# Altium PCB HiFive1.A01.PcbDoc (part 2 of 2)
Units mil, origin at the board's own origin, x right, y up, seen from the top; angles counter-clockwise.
Board outline 2700 x 2100 mil, 4 copper layers (Top Layer, GND, Power, Bottom Layer), stack 60.6 mil thick; 123 components, 93 nets, 495 pads, 264 vias.
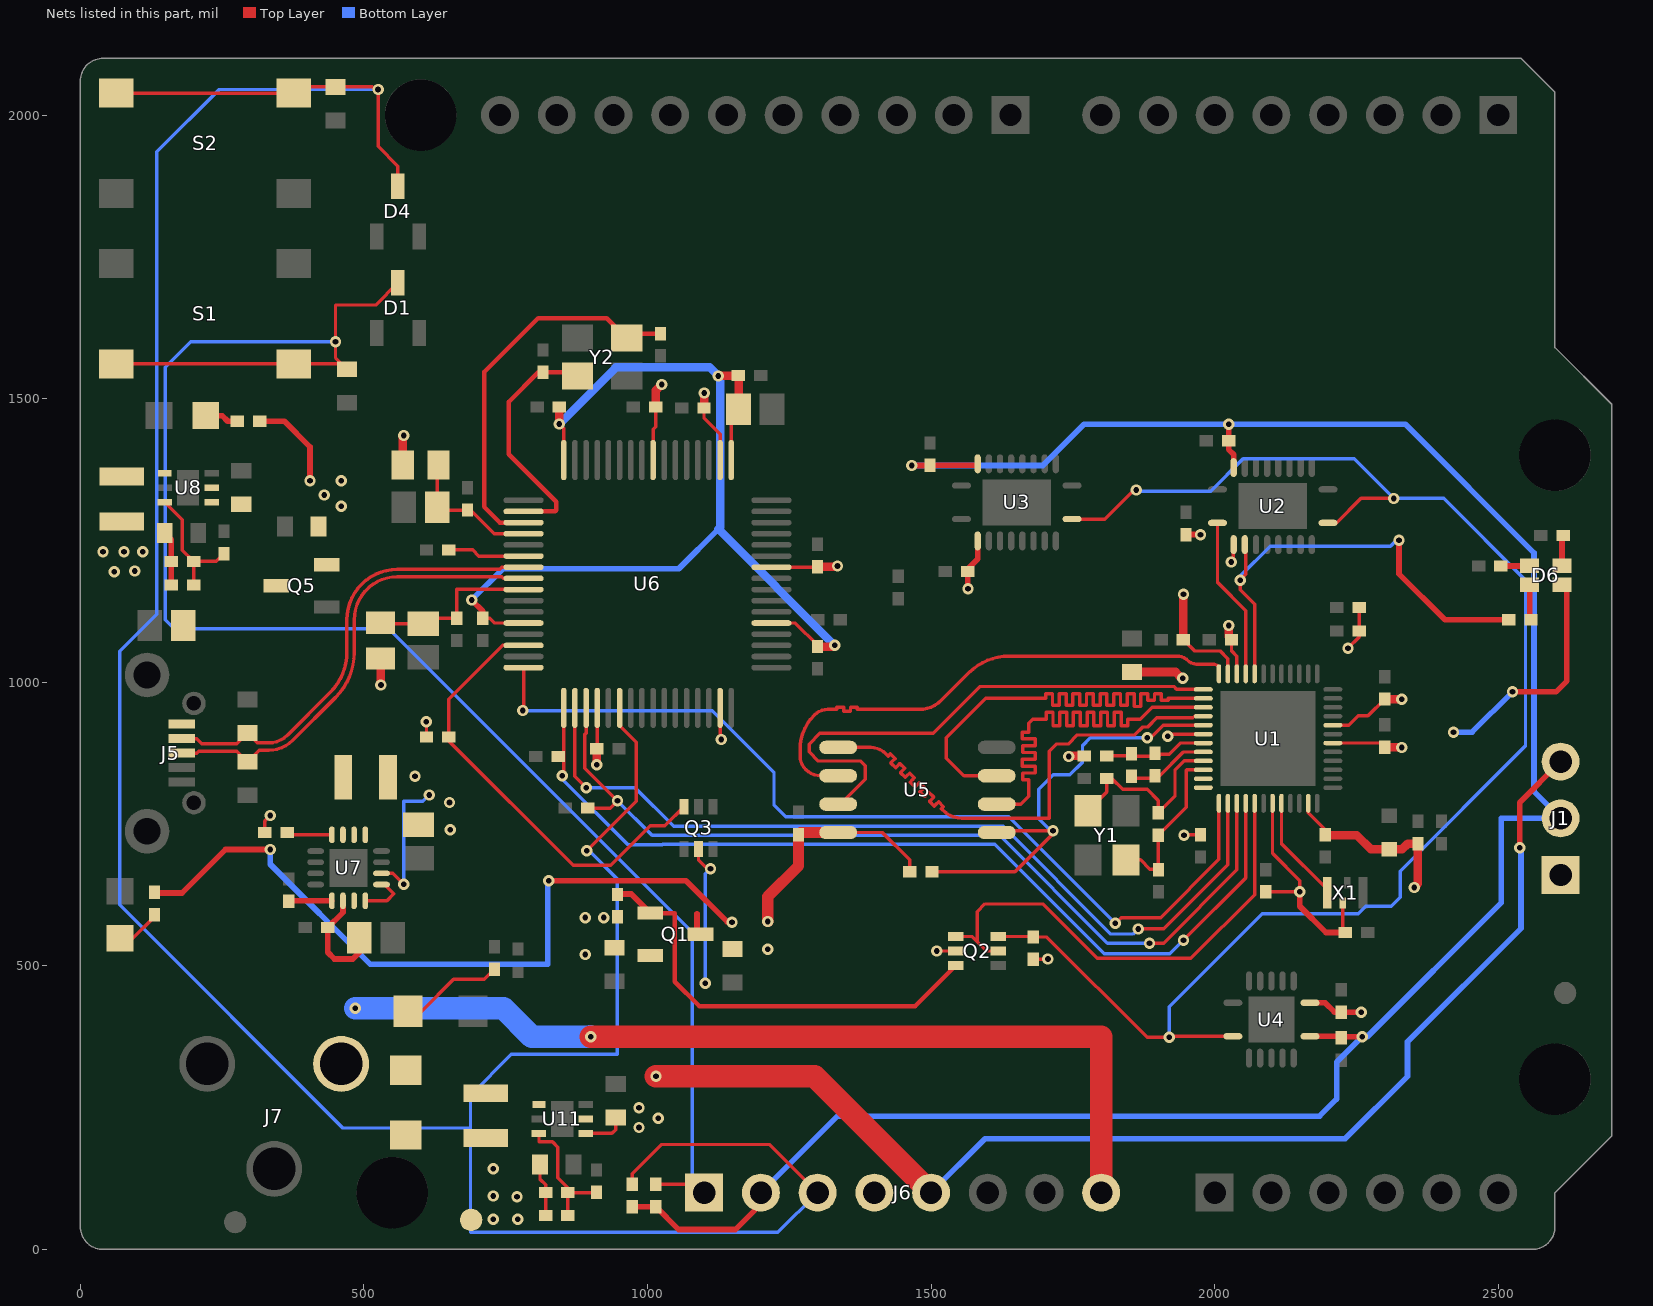
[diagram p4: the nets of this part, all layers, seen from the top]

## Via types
v1: diameter 20, hole 10, Top Layer to Bottom Layer, tented both sides, 264 vias

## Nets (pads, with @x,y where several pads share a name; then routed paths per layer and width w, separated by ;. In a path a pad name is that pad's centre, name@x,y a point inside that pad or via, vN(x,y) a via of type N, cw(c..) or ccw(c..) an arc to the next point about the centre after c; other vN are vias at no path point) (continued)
GPIO_22: R19.2 U1.44 U2.3 | length 842.3
  Top Layer w6: U2.3@2053.2,1242.56 2055,1240.76 2055,1190 v1(2045,1180) 2045,1163 2070.55,1137.45 U1.44@2070.55,1014.8
  Top Layer w10: v1(2325,1250) 2325,1191 2406,1110 R19.2@2518.31,1110
  Bottom Layer w6: v1(2045,1180) 2045,1187.23 2097.77,1240 2310,1240 2320,1250 v1(2325,1250)
GPIO_23: U1.45 U2.1 | length 286.8
  Top Layer w6: U2.1@2004.97,1280.94 2004.97,1176.03 2054.8,1126.2 U1.45@2054.8,1014.8
JTAG_TCK: U1.13 U6.16 | length 1638
  Top Layer w6: v1(780,950) 781.5,951.5 U6.16@781.5,1025.58 ; v1(1825,575) 1835,585 1905,585 2007.56,687.56 U1.13@2007.56,786.46
  Bottom Layer w6: v1(780,950) 1114,950 1223,841 1223,784 1244,763 1637,763 v1(1825,575)
JTAG_TDI: R12.1 U1.16 U6.17 | length 1656.2
  Top Layer w6: R12.1@842.68,869 R12.1@852.36,869 ; v1(850,835) 852.36,837.36 R12.1@852.36,869 ; U6.17@852.36,954.71 R12.1@852.36,869 ; v1(1945,545) 2054.8,654.8 U1.16@2054.8,786.46
  Bottom Layer w6: v1(850,835) 850,829.13 965.62,713.51 1026.51,713.51 1027,714 1612,714 1805,521 1921,521 v1(1945,545)
JTAG_TDO: U1.14 U6.18 | length 1546.9
  Top Layer w6: U6.18@872.05,954.71 872.05,833.95 v1(892,814) ; v1(1865,565) 1910,565 2023.31,678.31 U1.14@2023.31,786.46
  Bottom Layer w6: v1@891.32,814.68 v1(892,814) 978,814 1046,746 1627.13,746 1817.13,556 1856,556 v1(1865,565)
JTAG_TMS: R10.1 U1.15 U6.19 | length 1613
  Top Layer w6: U6.19@891.73,954.71 891.73,910.35 889.5,908.12 889.5,848.63 894.09,844.04 894.09,843.91 v1(947,791) 934,778 R10.1@894.68,778 ; v1(1885,540) 1910,540 2039.06,669.06 U1.15@2039.06,786.46
  Bottom Layer w6: v1(947,791) 1008,730 1621,730 1811,540 v1(1885,540)
LFCLK: U1.20 X1.3 | length 191.2
  Top Layer w6: U1.20@2117.8,786.46 2117.8,715.33 2198.5,634.63 X1.3@2198.5,628.64
NetC8_2: C8.2 C9.2 U1.8 | length 149.3
  Top Layer w6: C8.2@1850,830.31 1891.8,830.31 1895,833.51 1901.54,833.51 1945.04,877.01 U1.8@1980,877.01
NetC12_1: C12.1 R4.1 U1.9 Y1.1 | length 360.1
  Top Layer w6: Y1.1@1776.54,756.46 Y1.1@1776.54,773.31 1809.68,806.46 C12.1@1809.68,830 1819,830 1838,811 1881,811 1900.56,791.44 R4.1@1900.56,769.68 1930,799.12 1930,845 1946.26,861.26 U1.9@1980,861.26
NetC13_1: C13.1 R4.2 U1.10 Y1.3 | length 308.1
  Top Layer w6: Y1.3@1856.6,673.56 Y1.3@1843.46,686.69 1869.31,686.69 1885.88,670.12 1900.56,670.12 R4.2@1900.56,730.31 1950,779.75 1950,845 1950.51,845.51 U1.10@1980,845.51
NetC39_1: C39.1 U6.2 Y2.1 | length 430.1
  Top Layer w8: U6.2@781.5,1301.17 837.17,1301.17 839,1303 839,1318 755.08,1401.92 755.08,1494.08 807.32,1546.32 C39.1@816,1546.32 870.13,1546.32 Y2.1@876.69,1539.75
NetC40_1: C40.1 U6.3 Y2.3 | length 687.2
  Top Layer w8: U6.3@781.5,1281.49 739.51,1281.49 712,1309 712,1547 807,1642 927.99,1642 Y2.3@963.31,1606.68 972.68,1606.68 980.68,1614.68 C40.1@1023,1614.68
NetC45_1: C45.1 U7.9 | length 76.4
  Top Layer w10: C45.1@367.45,613.59 368.59,614.74 U7.9@443.4,614.74
NetC48_2: C48.2 R35.2 R36.1 U8.3 | length 226.2
  Top Layer w6: U8.3@148.66,1317.42 180,1286.08 180,1232.7 R35.2@199.69,1213.01 ; C48.2@199.69,1171.51 R35.2@199.69,1213.01 ; R36.1@253.16,1226.7 239.47,1213.01 R35.2@199.69,1213.01
NetC54_2: C54.2 R37.2 R39.1 U11.3 | length 236.8
  Top Layer w6: U11.3@808.66,204.41 808.66,189.5 832.5,189.5 842,180 842,126 859.69,108.31 R37.2@859.69,100 ; C54.2@859.69,60 R37.2@859.69,100 ; R39.1@909.37,92.37 909.37,100 R37.2@859.69,100
NetD6_1: D6.1 R19.1 | length 68.5
  Top Layer w10: R19.1@2557.68,1110 2555.46,1112.23 D6.1@2555.46,1172.13 D6.1@2560.87,1172.13
NetD6_2: D6.2 R18.1 | length 51
  Top Layer w10: R18.1@2504.68,1205 2554.87,1205 D6.2@2555.46,1205.59
NetD6_3: D6.3 R17.1 | length 54.1
  Top Layer w8: R17.1@2612.54,1257.08 R17.1@2614.37,1258.91
  Top Layer w10: D6.3@2612.54,1205.59 R17.1@2612.54,1257.08
NetD9_2: D9.2 R27.2 | length 59.5
  Top Layer w10: D9.2@221.34,1470 250,1470 260,1460 R27.2@276.69,1460
NetD10_2: D10.2 R28.2 | length 80.1
  Top Layer w6: D10.2@70,548.66 92.66,548.66 130.76,586.76 R28.2@130.76,590.31
NetD13_2: D13.2 J7.1
NetL1_1: L1.1 U7.1 U7.2 U7.3
NetL2_1: L2.1 U8.1
NetL3_1: L3.1 U11.1
NetQ1_1: Q1.1 Q2.3 R9.1 | length 769.9
  Top Layer w8: Q1.1@1005,593 1048,593 1048,472 1091,429 1472.19,429 Q2.3@1543.6,500.41
  Top Layer w10: R9.1@956,626.68 971.32,626.68 Q1.1@1005,593
NetQ3_6: Q3.6 R23.2 U6.14 | length 793.1
  Top Layer w6: U6.14@781.5,1064.95 744.95,1064.95 649.69,969.69 R23.2@649.69,903.22 649.69,896.31 869,677 935,677 1005,747 1030.79,747 Q3.6@1064.41,780.62
NetR24_1: R24.1 U6.6 | length 136.3
  Top Layer w6: R24.1@649.68,1233.22 691.78,1233.22 702.57,1222.43 U6.6@781.5,1222.43
NetR31_2: R31.2 U7.4 | length 80.4
  Top Layer w6: R31.2@364.69,735 368.81,730.88 U7.4@443.4,730.88
PLL_AVDD: C8.1 C9.1 R1.2 U1.7 | length 180
  Top Layer w6: R1.2@1809.69,870 1849.68,870 1850,869.68 1901.8,869.68 1905,872.88 1919.75,872.88 1939.63,892.76 U1.7@1980,892.76
QSPI_CS0: R13.1 U1.5 U5.1 | length 793.5
  Top Layer w6: R13.1@1501.68,665.93 1647.93,665.93 1715,733 v1(1715,738) 1639,738 1634,733 1617.76,733 U5.1@1615.76,735 ; v1(1881,902) 1887.13,902 1909.38,924.25 U1.5@1980,924.25
  Bottom Layer w6: v1(1715,738) 1715,734 1713,736 1690,759 1690,811 1715.75,836.75 1744.75,836.75 1767,859 1767,888 1781,902 v1(1881,902)
QSPI_DQ0: U1.4 U5.5 | length 952.3
  Top Layer w6: U5.5@1336.24,885 1393.44,885 cw(c1393.44,847.44) 1420,874 1424.26,869.78 1428.02,873.57 1436.55,865.13 1432.79,861.34 1429.04,857.54 1437.56,849.1 1441.32,852.89 1445.07,856.69 1453.6,848.24 1449.85,844.45 1446.09,840.66 1454.62,832.21 1458.37,836.01 1462.13,839.8 1470.66,831.36 1466.9,827.56 1463.15,823.77 1471.67,815.33 1475.43,819.12 1479.18,822.91 1487.71,814.47 1483.96,810.68 1480.2,806.88 1488.73,798.44 1492.48,802.23 1496.24,806.03 1504.77,797.58 1501.01,793.79 1497.25,790 1505.78,781.56 1509.54,785.35 1513.29,789.14 1521.82,780.7 1518.07,776.91 1521,774 ccw(c1554.02,807.02) 1554.02,760.32 1708,760.32 1708,878 1721,891 1742,891 1758,907 1859.13,907 1873.13,921 1881.96,921 1898,937.04 1961.7,937.04 1964.66,940 U1.4@1980,940
QSPI_DQ1: U1.3 U5.2 | length 951.4
  Top Layer w6: U5.2@1615.76,785 1658,785 1672,799 1672,822 1672,828 1661.79,828 1661.79,840 1672,840 1683.43,840 1683.43,852 1672,852 1660.57,852 1660.57,864 1672,864 1683.43,864 1683.43,876 1672,876 1661.79,876 1661.79,888 1672,888 1683.43,888 1683.43,900 1672,900 1660.57,900 1660.57,912 1672,912 1672,917 1672,927.93 1679.07,935 1703,935 1703,946.9 1715,946.9 1715,935 1715,923.1 1727,923.1 1727,935 1727,946.9 1739,946.9 1739,935 1739,923.1 1751,923.1 1751,935 1751,946.9 1763,946.9 1763,935 1763,923.1 1775,923.1 1775,935 1775,946.9 1787,946.9 1787,935 1787,923.1 1799,923.1 1799,935 1799,946.9 1811,946.9 1811,935 1811,923.1 1823,923.1 1823,935 1823,946.9 1835,946.9 1835,935 1835,923.1 1847,923.1 1847,935 1853,935 1868.92,935 1889.67,955.75 U1.3@1980,955.75
QSPI_DQ2: U1.2 U5.3 | length 951.4
  Top Layer w6: U5.3@1615.76,835 1558,835 1527,866 1527,902 1596.5,971.5 1651,971.5 1702,971.5 1702,979.74 1714,979.74 1714,971.5 1714,959.61 1726,959.61 1726,971.5 1726,979.74 1738,979.74 1738,971.5 1738,959.61 1750,959.61 1750,971.5 1750,979.76 1762,979.76 1762,971.5 1762,959.61 1774,959.61 1774,971.5 1774,979.75 1786,979.75 1786,971.5 1786,959.61 1798,959.61 1798,971.5 1798,979.74 1810,979.74 1810,971.5 1810,959.61 1822,959.61 1822,971.5 1822,979.74 1834,979.74 1834,971.5 1834,959.61 1846,959.61 1846,971.5 1846,979.76 1858,979.76 1858,971.5 1858,957.2 1870,957.2 1870,971.5 1870,979.75 1882,979.75 1882,971.5 1882,968.45 1894,968.45 1894,971.5 1894,979.78 1906,979.78 1906,971.5 1906,968.45 1918,968.45 1918,971.5 1924,971.5 U1.2@1980,971.5
QSPI_DQ3: U1.1 U5.7 | length 952.1
  Top Layer w6: U5.7@1336.24,785 1340,785 1384,829 1384,853 1376,861 1301,861 1285,877 1285,891 1304,910 1504,910 1586.48,992.48 1927.52,992.48 1932.76,987.24 U1.1@1980,987.24
QSPI_SCK: U1.48 U5.6 | length 952.6
  Top Layer w6: U5.6@1336.24,835 1305.56,835 cw(c1305.56,872.56) 1279,846 cw(c1303.14,870.14) 1269,870.14 1269,881.64 cw(c1354.36,881.64) 1294,942 cw(c1318.14,917.86) 1318.14,952 1328,952 1334,952 1334,955.5 1346,955.5 1346,952 1346,948.5 1358,948.5 1358,952 1358,955.5 1370,955.5 1370,952 1382,952 1479.37,952 ccw(c1479.37,1006.63) 1518,968 1566.71,1016.71 cw(c1637.42,946) 1637.42,1046 1933.69,1046 cw(c1933.69,1018.69) 1953,1038 ccw(c1967.49,1052.49) 1967.49,1032 1996.55,1032 cw(c1996.55,1016.43) 2007.56,1027.44 U1.48@2007.56,1014.8
RESET: D4.3 D5.1 J6.3 R6.2 S2.3 S2.4 U6.22 | length 5482.3
  Top Layer w6: S2.4@63.5,2038.58 S2.3@376.5,2038.58 387.44,2049.53 D5.1@450,2049.53 514.53,2049.53 519.06,2045 v1(525,2045) 525,1945 560,1910 D4.3@560,1874.29 ; v1(893,703) 980,790 980,894 950.79,923.21 U6.22@950.79,954.71 ; R6.2@973.1,114.69 973.1,133.1 1025,185 1215,185 J6.3@1300,100
  Bottom Layer w6: v1(525,2045) 245,2045 135,1935 135,1120 69.35,1054.35 69.35,607.65 463,214 688,214 ; v1(893,703) 897,703 947,653 947,344 760,344 688,272 688,214 ; J6.3@1300,100 1230,30 688,30 688,214
TSLR_OE: Q2.6 R11.2 U2.10 U3.10 U4.8 | length 2747.3
  Top Layer w6: Q2.6@1618.4,551.59 1679.09,551.59 R11.2@1680,550.69 1704.31,550.69 1881,374 v1(1920,374) 1921.76,375.76 U4.8@2032.08,375.76 ; U3.10@1748.54,1287.56 1806.56,1287.56 1858,1339 v1(1862,1339) ; U2.10@2199.85,1280.94 2214.94,1280.94 2258,1324 v1(2316,1324)
  Bottom Layer w6: v1(1862,1339) 1864,1337 1993,1337 2050,1394 2246,1394 v1(2316,1324) 2404,1324 2548,1180 2548,888 2327,667 2327,621 2311,605 2266,605 2253,592 2084,592 1920,428 v1(1920,374)
USB_D_N: D8.1 J5.2 U6.7 | length 815.2
  Top Layer w6: J5.2@178.74,900.59 205.36,900.59 214.45,891.5 275.85,891.5 D8.1@294.82,910.47 312.29,893 332.05,893 ccw(c332.05,939.95) 365.25,906.75 440.71,982.21 ccw(c370,1052.92) 470,1052.92 470,1110 cw(c559,1110) 559,1199 739.32,1199 743.06,1202.75 U6.7@781.5,1202.75
USB_D_P: D7.1 J5.3 U6.8 | length 813.8
  Top Layer w6: J5.3@178.74,875 205.36,875 208.86,878.5 275.85,878.5 D7.1@294.82,859.53 315.29,880 332.05,880 ccw(c332.05,939.95) 374.44,897.56 449.9,973.02 ccw(c370,1052.92) 483,1052.92 483,1110 cw(c559,1110) 559,1186 743.06,1186 746,1183.06 U6.8@781.5,1183.06
VBUS: C35.1 J5.1 Q5.3
VCORE_FT: C29.1 C30.1 C31.1 C37.1 C38.1 U6.12 U6.37 U6.49 U6.64 | length 1910.3
  Top Layer w6: C29.1@709.48,1112.9 722.1,1112.9 730.68,1104.32 U6.12@781.5,1104.32 ; v1(844.68,1455.32) 852.36,1447.64 U6.64@852.36,1391.72 ; U6.49@1147.64,1391.72 1147.64,1468.62 C37.1@1160.47,1481.46 ; U6.37@1218.5,1104.32 1260.68,1104.32 1300,1065 C31.1@1300,1062.9
  Top Layer w10: v1(690,1145) 709.48,1125.52 C29.1@709.48,1112.9
  Top Layer w15: v1(844.68,1455.32) C30.1@844.68,1485 ; v1(1125,1540) 1159.64,1540 C38.1@1160.32,1540.68 1160.47,1540.52 C37.1@1160.47,1481.46 ; C31.1@1300,1062.9 1327.9,1062.9 v1(1330,1065)
  Bottom Layer w10: v1(690,1145) 745,1200 1055,1200 1125,1270
  Bottom Layer w15: v1(844.68,1455.32) 944.37,1555 1110,1555 v1(1125,1540) 1128.5,1536.5 1128.5,1273.5 1125,1270 v1(1330,1065)
VDD_1V8: C1.1 C2.1 C3.1 C5.1 C17.1 C54.1 C55.1 D3.1 L3.2 Q2.2 Q3.2 R1.1 R2.2 R5.2 R37.1 TP1.1 U1.6 U1.19 U1.23 U1.30 U1.46 X1.4 | length 1530.2
  Top Layer w6: C55.1@810.47,150 810.47,123.53 820.32,113.68 R37.1@820.32,100 C54.1@820.32,60 ; Q3.2@1090,705.82 1090,686 1105,671 v1(1111,671) ; v1(1510,526) Q2.2@1543.6,526 ; v1(1917,905) 1920.5,908.5 U1.6@1980,908.5 ; C2.1@2029.68,1075 2029.68,1055.32 2039.06,1045.94 U1.46@2039.06,1014.8 ; R2.2@2090,630.31 v1(2150,630.31) 2150,650 2102.05,697.95 U1.19@2102.05,786.46 ; U1.23@2165.04,786.46 2165.04,770.02 2195,740.06 C5.1@2195,731.17 C5.1@2196.17,730 ; U1.30@2208.35,892.76 2292.56,892.76 C3.1@2300,885.31 ; X1.4@2226.06,610.92 2226.06,562.84 C17.1@2230.32,558.59
  Top Layer w10: v1(2150,630.31) 2150,605 2196.41,558.59 C17.1@2230.32,558.59
  Top Layer w15: v1(1743,869) 1744,870 R1.1@1770.32,870 R1.1@1768.82,871.5 ; C1.1@1854.15,1018 1931,1018 1942,1007 1943,1008 v1(1944,1007) ; v1(2025,1100) 2025,1080.31 2030,1075.31 C2.1@2029.68,1075 ; C5.1@2196.17,730 2250.94,730 2275.47,705.47 D3.1@2307.74,705.47 ; C3.1@2300,885.31 2300.31,885 v1(2330,885) ; D3.1@2310,703.21 D3.1@2307.74,705.47 ; v1(2352,638) 2358.49,644.49 R5.2@2358.49,715.31 2340.31,715.31 2330.47,705.47 D3.1@2307.74,705.47
  Bottom Layer w6: v1(1102,469) 1102,662 v1(1111,671)
  other v1: 728,53 771,53 770,93 728,94 728,142
VDD_3V3: C4.1 C10.1 C21.1 C26.1 C27.1 C28.1 C34.1 C48.1 C49.1 C50.1 FB1.1 FB2.1 J1.1 J6.4 L2.2 Q1.2 R9.2 R11.1 R23.1 R35.1 U2.2 U3.2 U4.1 U6.20 U6.31 U6.42 U6.50 U6.56 | length 1045.5
  Top Layer w6: v1(610,930) 610.32,929.68 R23.1@610.32,903.22 ; C26.1@910.32,882.7 911.42,883.8 U6.20@911.42,954.71 ; U6.56@1009.84,1391.72 1010,1391.88 1010,1446 1014.5,1450.5 C28.1@1014.5,1485.45 ; C34.1@1099.68,1483.22 1099.68,1465.32 1127.95,1437.05 U6.50@1127.95,1391.72 ; U6.31@1127.95,954.71 1127.95,897.05 v1(1130,899.09) ; U6.42@1218.5,1202.75 1299.21,1202.75 C27.1@1300,1203.53 ; R11.1@1680,511.32 1705.32,511.32 v1(1706,512) ; v1(2029,1212) 2032,1212 2033,1213 2033,1242.05 U2.2@2033.51,1242.56
  Top Layer w10: C50.1@148.66,1263.12 160.32,1251.47 R35.1@160.32,1213.01 C48.1@160.32,1171.51 ; v1(1565,1165) 1564.68,1165.32 C4.1@1564.68,1195 1564.68,1199.68 1582.2,1217.2 U3.2@1582.2,1249.17 ; C10.1@1949.68,1260.32 1974.68,1260.32 v1(1975,1260) ; U4.1@2167.91,434.82 2194.82,434.82 2211.38,418.25 C21.1@2223.2,418.25 v1(2258.25,418.25)
  Top Layer w15: FB1.1@529.48,1041.72 529.48,995.52 v1(530,995) ; FB2.1@568.5,1383.22 568.5,1433.5 v1(570,1435) ; v1(910.32,854.68) C26.1@910.32,882.7 ; C28.1@1014.5,1485.45 1014.5,1514.5 v1(1025,1525) ; C34.1@1099.68,1483.22 1099.68,1509.68 v1(1100,1510) ; C27.1@1300,1203.53 1333.53,1203.53 v1(1335,1205)
  other v1: 890,520 890,585 923,585 60,1195 96,1196 40,1230 77,1230 110,1230
VDD_3V3_MOFF: C18.1 C19.1 C20.1 C23.1 C51.1 D6.4 Q1.3 R7.2 R8.2 R13.2 R28.1 U1.11 U1.12 U1.32 U1.47 U5.8 | length 2636.2
  Top Layer w6: U5.8@1336.24,735 1414,735 1462.31,686.69 R13.2@1462.31,665.93 ; C20.1@1944.87,1075 1964.87,1055 2010,1055 2023.31,1041.69 U1.47@2023.31,1014.8 ; v1(1946,730) 1947.17,731.17 C19.1@1975,731.17 ; U1.32@2208.35,924.25 2236.38,924.25 2252.8,940.67 2270.35,940.67 C18.1@2300,970.32 ; v1(2235,1060) 2254.69,1079.69 R7.2@2254.69,1090 R8.2@2254.69,1131.51
  Top Layer w10: R28.1@130.76,630.65 133.1,628.31 179.24,628.31 255.93,705 v1(335,705) ; v1(826,650) 1068,650 1141,577 v1(1149,577) ; Q1.3@1087.24,555.6 1087.24,591.76 ; v1(2525,983) 2601.7,983 2621,1002.3 2621,1163.67 D6.4@2612.54,1172.13
  Top Layer w15: C20.1@1944.87,1075 1945,1075.13 v1(1945,1155) ; C18.1@2300,970.32 2329.68,970.32 v1(2330,970)
  Top Layer w20: v1(1212,578) 1212,622 1266.19,676.19 C23.1@1266.19,731.32 1269.87,735 U5.8@1336.24,735
  Bottom Layer w10: v1(335,705) 335,679 511,503 824,503 824,648 v1(826,650) ; v1(2421,912) 2454,912 v1(2525,983)
  other v1: 1212,529
VDD_5V0: C42.1 C46.1 C47.1 C52.1 J1.3 J6.5 L1.2 Q5.2 R27.1 R31.1 U7.14 U8.4 U8.5 U11.4 U11.5 | length 2684.2
  Top Layer w6: R31.1@325.32,735 325.32,755.32 v1(335,765) ; U7.14@531,662.96 551.04,662.96 v1(570,644) ; U11.4@891.34,204.41 937.41,204.41 944,211 C52.1@944,232.47
  Top Layer w10: R27.1@316.06,1460 360,1460 405,1415 v1(405,1355) ; v1(2538,708) 2538,788 J1.3@2610,860
  Top Layer w40: v1(1015,305) 1295,305 J6.5@1500,100
  Bottom Layer w6: v1(570,644) 570,790 604,790 v1(615,801)
  Bottom Layer w10: J6.5@1500,100 1595,195 2230,195 2340,305 2340,366 2540,566 2540,706 v1(2538,708)
  other v1: 985,215 1019,231 985,250 652,740 651,788 590,834 460,1310 430,1330 460,1355
VDD_DCIN: C43.1 C44.1 D12.1 D13.1 J6.8 R30.2 U7.10 U7.11 U7.12 U7.13 | length 2075.3
  Top Layer w6: U7.12@502.46,614.74 540.74,614.74 553,627 536.72,643.28 U7.13@531,643.28 ; D12.1@575.23,420 D12.1@577.91,420 602,420 658,476 712.01,476 R30.2@730,493.99
  Top Layer w10: U7.10@463.09,614.74 463.09,594.22 C44.1@436.19,567.33 436.19,523.81 448,512 480.37,512 491.47,523.1 C43.1@491.47,549.61
  Top Layer w40: v1(900,375) 1800,375 J6.8@1800,100
  Bottom Layer w40: v1(485,425) 746,425 796,375 v1(900,375) v1@899,376
VDD_IOREF: C6.1 C11.1 C22.1 J1.2 J6.2 R3.1 R6.1 U2.19 U3.19 U4.14 | length 4097.3
  Top Layer w10: R6.1@973.1,75.32 R3.1@1014.61,75.32 1054.92,35 1155,35 1200,80 J6.2@1200,100 ; v1(1466,1382) 1498.06,1382 C6.1@1498.38,1382.32 1579.52,1382.32 U3.19@1582.2,1385 ; v1(2025,1455) 2024.68,1454.68 C11.1@2024.68,1425.8 2024.68,1410.32 2033.51,1401.49 U2.19@2033.51,1378.39 ; U4.14@2167.91,375.76 2220.24,375.76 C22.1@2223.2,372.81 2225.39,375 v1(2260,375) ; C6.1@1498.38,1385 1498.38,1386.62 1500,1385 C6.1@1498.38,1385
  Bottom Layer w10: J6.2@1200,100 1335,235 2185,235 2215,265 2215,330 v1(2260,375) 2269,375 2505,611 2505,760 J1.2@2610,760 2563,807 2563,1228 2336,1455 v1(2025,1455) 1770,1455 1697,1382 v1(1466,1382)
VDD_PAD_EN: Q2.1 Q2.5 U1.17 | length 880.3
  Top Layer w6: Q2.1@1543.6,551.59 1572.41,551.59 1581.5,542.5 ; Q2.5@1618.4,526 1598,526 1581.5,542.5 ; U1.17@2070.55,786.46 2070.55,625.55 1958,513 1793,513 1697,609 1595,609 1581.5,595.5 1581.5,542.5
VPHY_FT: C32.1 C33.1 FB2.2 U6.4 | length 247
  Top Layer w6: FB2.2@631.5,1383.22 629.53,1381.25 C32.1@629.53,1308.25 634.24,1303.53 C33.1@682.84,1303.53 688.34,1303.53 729.99,1261.88 781.41,1261.88 U6.4@781.5,1261.8
VPLL_FT: C24.1 C25.1 FB1.2 U6.9 | length 308.4
  Top Layer w6: FB1.2@529.48,1104.71 531.45,1102.75 C24.1@604.45,1102.75 614.61,1112.9 C25.1@663.67,1112.9 663.67,1164 780.87,1164 U6.9@781.5,1163.38
WAKE: D1.3 D2.1 J6.1 R3.2 S1.1 S1.2 | length 3124.7
  Top Layer w6: S1.2@63.5,1561.42 S1.1@376.5,1561.42 D2.1@460.15,1561.42 ; D2.1@470,1551.56 D2.1@460.15,1561.42 ; D1.3@560,1704.29 520.71,1665 450,1665 v1(450,1600) 450,1571.56 D2.1@460.15,1561.42 ; R3.2@1014.61,114.69 1085.32,114.69 J6.1@1100,100
  Bottom Layer w6: v1(450,1600) 195,1600 150,1555 150,1110 166.09,1093.91 544.09,1093.91 1079,559 1079,121 J6.1@1100,100
pads on no net: D1.2 D4.2 J3.8 J4.1 J5.4 Q3.3 Q3.4 Q3.5 U4.6 U4.9 U6.21 U6.23 U6.24 U6.26 U6.27 U6.28 U6.29 U6.30 U6.32 U6.33 U6.34 U6.36 U6.40 U6.41 U6.43 U6.44 U6.45 U6.46 U6.48 U6.52 U6.53 U6.54 U6.55 U6.57 U6.58 U6.59 U6.60 U6.61 U6.62 U6.63 X1.1

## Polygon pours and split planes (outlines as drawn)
VDD_DCIN on Top Layer "VDD_DCIN_L01_P060" (solid, remove dead copper, pour order 60): 476,630 510,630 520,620 520,480 554,480 590,480 609,480 624,480 635,480 635,240 536,240 535,239 519,255 515,255 515,389 514,390 470,390 470,523 470,577 476,577
NetD13_2 on Top Layer "NETD13_2_L01_P058" (solid, remove dead copper, pour order 58): 410,380 510,380 510,250 530,230 635,230 635,170 410,170
VBUS on Top Layer "VBUS_L01_P008" (solid, remove dead copper, pour order 8): 156,919 234,919 246,935 246,1044 335,1133 380,1133 380,1199 380,1210 369,1210 312,1210 301,1210 226,1135 225,1136 156,1136
NetL1_1 on Top Layer "NETL1_1_L01_P012" (solid, remove dead copper, pour order 12): 513,717 455,717 455,743 455,770 445,770 425,770 425,790 425,880 491,880 496,880 513,880 513,858
VDD_5V0 on Top Layer "VDD_5V0_L01_P016" (solid, remove dead copper, pour order 16): 520,879 526,879 570,879 621,828 672,828 672,778 672,770 672,720 671,719 669,721 520,721
GND on Top Layer "GND_L01_P018" (solid, remove dead copper, pour order 18): 670,715 670,510 526,510 526,587 560,665 550,675 503,675 503,705 502,706 504,708 520,708 552,708 559,715
GND on Top Layer "GND_L01_P020" (solid, remove dead copper, pour order 20): 445,710 400,710 380,710 350,710 350,674 350,633 387,633 432,633 432,634 447,649
VDD_5V0 on Top Layer "VDD_5V0_L01_P022" (solid, remove dead copper, pour order 22): 876,219 915,219 921,219 921,210 921,200 1035,200 1035,260 984,260 915,260 895,240 876,240
NetL3_1 on Top Layer "NETL3_1_L01_P026" (solid, remove dead copper, pour order 26): 825,301 825,247 792,247 764,236 667,236 667,300 668,301 793,301
GND on Top Layer "GND_L01_P028" (solid, remove dead copper, pour order 28): 852,202 852,134 866,120 870,120 930,120 930,165 911,165 895,181 891,185 870,185 870,199 867,202
GND on Top Layer "GND_L01_P030" (solid, remove dead copper, pour order 30): 971,312 971,268 972,267 971,268 919,268 919,258 906,245 905,244 860,245 860,335 971,335
VDD_3V3 on Top Layer "VDD_3V3_L01_P038" (solid, remove dead copper, pour order 38): 1028,505.07 1028,600.07 878,600.07 873,600.07 873,505.07
VDD_5V0 on Top Layer "VDD_5V0_L01_P044" (solid, remove dead copper, pour order 44): 390,1175 475,1175 475,1375 390,1375 390,1175
VDD_5V0 on Top Layer "VDD_5V0_L01_P046" (solid, remove dead copper, pour order 46): 215,1355 255,1355 255,1350 260,1345 320,1345 395,1345 395,1305 320,1305 305,1290 215,1290 215,1355
GND on Top Layer "GND_L01_P048" (solid, remove dead copper, pour order 48): 340,1415 340,1350 170,1350 170,1415
NetL2_1 on Top Layer "NETL2_1_L01_P050" (solid, remove dead copper, pour order 50): 160,1355 160,1400 25,1400 25,1340 25,1330 100,1330 125,1355
VDD_3V3 on Top Layer "VDD_3V3_L01_P052" (solid, remove dead copper, pour order 52): 25,1320 125,1320 125,1305 140,1290 170,1290 170,1235 125,1235 125,1177 25,1177
GND on Top Layer "GND_L01_P054" (solid, remove dead copper, pour order 54): 190,1315 190,1245 385,1245 385,1300 325,1300 310,1285 215,1285 210,1290 210,1315
VDD_3V3_MOFF on Top Layer "VDD_3V3_MOFF_L01_P056" (solid, remove dead copper, pour order 56): 1960,835 2000,835 2000,750 2000,710 1930,710 1930,745 1960,745
VDD_3V3_MOFF on Top Layer "VDD_3V3_MOFF_L01_P040" (solid, remove dead copper, pour order 40): 1071,601 1071,505 1251,505 1251,601
VDD_1V8 on Top Layer "VDD_1V8_L01_P064" (solid, remove dead copper, pour order 64): 667,229 765,229 765,188 770,183 778,175 832,175 832,122 833,121 831,119 765,119 759,117 744,117 667,117 667,178.12
VDD_1V8 on Top Layer "VDD_1V8_L01_P066" (solid, remove dead copper, pour order 66): 667,20 795,20 795,121 667,121
GND on Top Layer "TOP_GND_POUR" (solid, remove dead copper, pour order 68): 1,0 6,0 2702,0 2702,2093 2700,2095 2699,2096 2,2096
GND on Bottom Layer "BOT_GND_POUR" (solid, remove dead copper, pour order 70): -1,1 2699,1 2697,3 2697,2102 0,2102
GND on GND (split plane): 40,2079.9 2531.68,2079.9 2579.9,2031.68 2579.9,1590 2580.29,1586.08 2581.43,1582.31 2583.29,1578.83 2585.79,1575.79 2679.9,1481.68 2679.9,208.32 2585.79,114.21 2583.29,111.17 2581.43,107.69 2580.29,103.92 2579.9,100 2579.9,40 2579.95,39.53 2579.61,36.1 2578.47,32.35 2576.63,28.89 2574.14,25.86 2571.11,23.37 2567.65,21.53 2563.9,20.39 2560.47,20.05 2560,20.1 40,20.1 39.53,20.05 36.1,20.39 32.35,21.53 28.89,23.37 25.86,25.86 23.37,28.89 21.53,32.35 20.39,36.1 20.05,39.53 20.1,40 20.1,2060 20.05,2060.47 20.39,2063.9 21.53,2067.65 23.37,2071.11 25.86,2074.14 28.89,2076.63 32.35,2078.47 36.1,2079.61 39.53,2079.95
VDD_3V3_MOFF on Power (split plane): 2325.84,1078.02 2325.93,1077.95 2325.99,1077.87 2326.96,1077.13 2327.9,1076.37 2328,1076.33 2328.08,1076.26 2329.2,1075.8 2330.31,1075.32 2330.41,1075.3 2330.51,1075.26 2331.71,1075.1 2332.91,1074.92 2333.02,1074.93 2333.12,1074.91 2444.91,1074.91 2444.91,680.09 1820.32,680.09 1919.66,784.45 2375,784.45 2377.61,784.8 2380.04,785.81 2382.13,787.41 2383.74,789.5 2384.74,791.93 2385.09,794.54 2385.09,935 2384.74,937.61 2383.74,940.04 2382.13,942.13 2380.04,943.73 2377.61,944.74 2375,945.09 2315.81,945.09 2126.72,1129.33 2125.72,1130.07 2124.73,1130.84 2124.67,1130.86 2124.61,1130.9 2123.45,1131.36 2122.3,1131.84 2122.23,1131.85 2122.17,1131.88 2120.92,1132.02 2119.69,1132.19 1928.4,1132.19 1928.21,1132.16 1928.02,1132.18 1926.91,1131.99 1925.79,1131.84 1925.61,1131.77 1925.42,1131.74 1924.4,1131.27 1923.36,1130.84 1923.2,1130.72 1923.03,1130.64 1922.16,1129.92 1921.27,1129.23 1921.15,1129.08 1921,1128.96 1347.02,510.09 1060.09,510.09 1060.09,614.91 1275,614.91 1275.14,614.93 1275.28,614.92 1276.45,615.1 1277.61,615.26 1277.74,615.31 1277.88,615.33 1278.96,615.82 1280.04,616.27 1280.16,616.35 1280.29,616.41 1281.2,617.15 1282.13,617.87 1282.22,617.98 1282.33,618.07 1815.42,1181.91 2226.28,1181.91
VDD_1V8 on Power (split plane): 2304.67,927.78 2305.67,927.03 2306.67,926.27 2306.73,926.24 2306.78,926.2 2307.94,925.74 2309.1,925.26 2309.17,925.25 2309.23,925.22 2310.47,925.08 2311.71,924.91 2364.91,924.91 2364.91,804.63 1915.33,804.63 1915.21,804.61 1915.09,804.62 1913.91,804.44 1912.72,804.28 1912.61,804.24 1912.48,804.22 1911.39,803.73 1910.29,803.28 1910.19,803.2 1910.08,803.15 1909.15,802.4 1908.2,801.67 1908.13,801.57 1908.03,801.49 1789.49,676.95 1788.79,675.99 1788.06,675.04 1788.01,674.93 1787.94,674.83 1787.51,673.71 1787.05,672.61 1787.04,672.49 1786.99,672.37 1786.86,671.18 1786.71,670 1786.72,669.88 1786.71,669.75 1786.9,668.57 1787.05,667.39 1787.1,667.27 1787.12,667.15 1787.6,666.06 1788.06,664.96 1788.14,664.86 1788.19,664.74 1788.94,663.82 1789.66,662.87 1789.76,662.79 1789.84,662.69 1790.8,661.99 1791.75,661.27 1791.87,661.22 1791.97,661.14 1793.08,660.71 1794.18,660.26 1794.31,660.24 1794.43,660.2 1795.61,660.07 1796.79,659.91 2444.91,659.91 2444.91,590.09 1705,590.09 1702.39,589.74 1699.96,588.73 1697.87,587.13 1312.87,202.13 1311.26,200.04 1310.26,197.61 1309.91,195 1309.91,20.1 709.09,20.1 709.09,32 709.09,64 709.09,164.91 1050,164.91 1052.61,165.26 1055.04,166.27 1057.13,167.87 1058.74,169.96 1059.74,172.39 1060.09,175 1060.09,213 1060.09,489.91 1351.42,489.91 1351.61,489.94 1351.8,489.92 1352.92,490.11 1354.04,490.26 1354.21,490.33 1354.4,490.36 1355.43,490.83 1356.47,491.27 1356.62,491.38 1356.79,491.46 1357.66,492.18 1358.56,492.87 1358.67,493.02 1358.82,493.14 1932.8,1112.01 2115.58,1112.01
VDD_5V0 on Power (split plane): 484.91,925 485.07,923.81 485.2,922.62 485.24,922.51 485.26,922.39 485.71,921.29 486.15,920.17 486.22,920.07 486.27,919.96 486.99,919.01 487.7,918.04 487.79,917.96 487.87,917.87 488.82,917.14 489.75,916.39 769.91,745.56 769.91,625 769.91,499 770.26,496.39 771.27,493.96 772.87,491.87 774.96,490.27 777.39,489.26 780,488.91 1039.91,488.91 1039.91,213 1039.91,185.09 320.09,185.09 320.09,1389.91 484.91,1389.91
VDD_3V3 on Power (split plane): 40,2079.9 2531.68,2079.9 2579.9,2031.68 2579.9,1590 2580.29,1586.08 2581.43,1582.31 2583.29,1578.83 2585.79,1575.79 2679.9,1481.68 2679.9,208.32 2585.79,114.21 2583.29,111.17 2581.43,107.69 2580.29,103.92 2579.9,100 2579.9,40 2579.95,39.53 2579.61,36.1 2578.47,32.35 2576.63,28.89 2574.14,25.86 2571.11,23.37 2567.65,21.53 2563.9,20.39 2560.47,20.05 2560,20.1 1330.09,20.1 1330.09,190.82 1709.18,569.91 2455,569.91 2457.61,570.26 2460.04,571.27 2462.13,572.87 2463.74,574.96 2464.74,577.39 2465.09,580 2465.09,670 2465.09,1085 2464.74,1087.61 2463.74,1090.04 2462.13,1092.13 2460.04,1093.74 2457.61,1094.74 2455,1095.09 2337.43,1095.09 2237.87,1198.98 2237.78,1199.05 2237.72,1199.13 2236.75,1199.87 2235.81,1200.63 2235.71,1200.67 2235.63,1200.74 2234.51,1201.2 2233.4,1201.68 2233.29,1201.7 2233.19,1201.74 2231.99,1201.9 2230.8,1202.08 2230.69,1202.07 2230.58,1202.09 1811.07,1202.09 1810.93,1202.07 1810.79,1202.08 1809.63,1201.9 1808.46,1201.74 1808.33,1201.69 1808.19,1201.67 1807.12,1201.18 1806.03,1200.74 1805.92,1200.65 1805.79,1200.59 1804.87,1199.85 1803.94,1199.13 1803.85,1199.02 1803.74,1198.93 1270.66,635.09 1050,635.09 1047.39,634.74 1044.96,633.73 1042.87,632.13 1041.27,630.04 1040.26,627.61 1039.91,625 1039.91,509.09 790.09,509.09 790.09,625 790.09,751.22 789.93,752.4 789.8,753.6 789.76,753.71 789.74,753.83 789.29,754.93 788.85,756.05 788.78,756.15 788.73,756.26 788.01,757.21 787.3,758.18 787.21,758.26 787.13,758.35 786.18,759.08 785.25,759.83 505.09,930.66 505.09,1400 504.74,1402.61 503.73,1405.04 502.13,1407.13 500.04,1408.74 497.61,1409.74 495,1410.09 310,1410.09 307.39,1409.74 304.96,1408.74 302.87,1407.13 301.27,1405.04 300.26,1402.61 299.91,1400 299.91,175 300.26,172.39 301.27,169.96 302.87,167.87 304.96,166.27 307.39,165.26 310,164.91 688.91,164.91 688.91,64 688.91,32 688.91,20.1 40,20.1 39.53,20.05 36.1,20.39 32.35,21.53 28.89,23.37 25.86,25.86 23.37,28.89 21.53,32.35 20.39,36.1 20.05,39.53 20.1,40 20.1,2060 20.05,2060.47 20.39,2063.9 21.53,2067.65 23.37,2071.11 25.86,2074.14 28.89,2076.63 32.35,2078.47 36.1,2079.61 39.53,2079.95

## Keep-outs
Keep-Out Layer:
  lines w1: 10,40 ccw(c40,40) 40,10 2560,10 ccw(c2560,40) 2590,40 2590,100 2690,200 2690,1490 2590,1590 2590,2040 2540,2090 40,2090 ccw(c40,2060) 10,2060 10,40

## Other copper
Top Layer:
  pour cut-out: 2007.56,987.8 2180.79,987.8 2180.79,813.46 2176.33,809 2008,809 2008,987.36
Power (plane layer: these items are gaps in the copper):
  lines w20: 699,11 699,32 699,64 699,175 ; 1320,10 1320,195 1705,580 1716,580 2455,580 2455,670 ; 699,175 580,175 310,175 310,1400 495,1400 495,925 780,751.22 780,625 780,499 1050,499 1050,213 1050,175 699,175 ; 2455,670 1796.79,670 1915.33,794.54 2375,794.54 2375,935 2311.71,935 2119.69,1122.1 2023.37,1122.1 1928.4,1122.1 1351.42,500 1050,500 1050,625 1275,625 1811.07,1192 2230.58,1192 2333.12,1085 2455,1085 2455,670

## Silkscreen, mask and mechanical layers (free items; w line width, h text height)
Top Overlay:
  text "RESET" at 465,1795 h60 r90
  text "WAKE" at 465,1590 h60 r90
  text "5.0V" at 2543,927 h70
  text "IOREF" at 2537,652 h80 r90
  text "3.3V" at 2543,550 h70
  text "GND" at 2578,396 h40
  text "WAKE" at 1120,170 h80 r90
  text "1.8V" at 651,78 h40
  text "GND" at 160,35 h40
Bottom Overlay:
  text "HiFive 1 Rev A01" at 835,1756 h100
  text "dev.sifive.com" at 842,1655 h100
Board Outline:
  the board outline again, w20
Fabrication:
  drawing of 307 lines, arcs and shapes, not listed
  text "Layer" at 3640.34,2560 h60
  text "Name" at 4050.26,2560 h60
  text "Material" at 4980,2560 h60
  text "Thickness" at 5839.77,2560 h60
  text "Constant" at 6489.6,2560 h60
  text "Board Layer Stack" at 7059.46,2560 h60
  text "1" at 3640.34,2440 h60
  text "Top Overlay" at 4050.26,2440 h60
  text "2" at 3640.34,2320 h60
  text "Top Solder" at 4050.26,2320 h60
  text "Solder Resist" at 4980,2320 h60
  text "0.50mil" at 5839.77,2320 h60
  text "3.5" at 6489.6,2320 h60
  text "3" at 3640.34,2200 h60
  text "Top Layer" at 4050.26,2200 h60
  text "Copper" at 4980,2200 h60
  text "1.40mil" at 5839.77,2200 h60
  text "4" at 3640.34,2080 h60
  text "Dielectric 1" at 4050.26,2080 h60
  text "FR-4" at 4980,2080 h60
  text "4.00mil" at 5839.77,2080 h60
  text "4.2" at 6489.6,2080 h60
  text "5" at 3640.34,1960 h60
  text "GND" at 4050.26,1960 h60
  text "Copper" at 4980,1960 h60
  text "1.40mil" at 5839.77,1960 h60
  text "6" at 3640.34,1840 h60
  text "Dielectric 2" at 4050.26,1840 h60
  text "47.00mil" at 5839.77,1840 h60
  text "4.2" at 6489.6,1840 h60
  text "7" at 3640.34,1720 h60
  text "Power" at 4050.26,1720 h60
  text "Copper" at 4980,1720 h60
  text "1.40mil" at 5839.77,1720 h60
  text "8" at 3640.34,1600 h60
  text "Dielectric 3" at 4050.26,1600 h60
  text "4.00mil" at 5839.77,1600 h60
  text "4.2" at 6489.6,1600 h60
  text "9" at 3640.34,1480 h60
  text "Bottom Layer" at 4050.26,1480 h60
  text "Copper" at 4980,1480 h60
  text "1.40mil" at 5839.77,1480 h60
  text "10" at 3640.34,1360 h60
  text "Bottom Solder" at 4050.26,1360 h60
  text "Solder Resist" at 4980,1360 h60
  text "0.50mil" at 5839.77,1360 h60
  text "3.5" at 6489.6,1360 h60
  text "11" at 3640.34,1240 h60
  text "Bottom Overlay" at 4050.26,1240 h60
Drill Drawing:
  circle w10: c3706.07,603.33 r33.33
  lines w10: 3672.73,136.67 3689.4,136.67 3689.4,120 3722.73,120 3722.73,136.67 3739.4,136.67 3739.4,170 3722.73,170 3722.73,186.67 3689.4,186.67 3689.4,170 3672.73,170 3672.73,136.67 ; 3672.73,336.67 3739.4,336.67 3706.07,270 3672.73,336.67 ; 3672.73,453.33 3706.07,420 3739.4,453.33 3706.07,486.67 3672.73,453.33 ; 3672.73,720 3706.07,736.67 3739.4,720 3722.73,753.33 3739.4,786.67 3706.07,770 3672.73,786.67 3689.4,753.33 3672.73,720 ; 3672.73,886.67 3689.4,886.67 3706.07,870 3722.73,886.67 3739.4,886.67 3722.73,903.33 3739.4,920 3722.73,920 3706.07,936.67 3689.4,920 3672.73,920 3689.4,903.33 3672.73,886.67
  lines w15: 3612.94,75 10822.98,75 ; 3612.94,975 10822.98,975 ; 4163.82,-75 4163.82,1125 ; 4753.66,-75 4753.66,1125 ; 5903.33,-75 5903.33,1125 ; 6409.2,-75 6409.2,1125 ; 7143,-75 7143,1125 ; 7732.85,-75 7732.85,1125 ; 8478.65,-75 8478.65,1125 ; 9278.43,-75 9278.43,1125 ; 3612.94,-75 10822.98,-75 10822.98,1125 3612.94,1125 3612.94,-75
  text "Symbol" at 3702.94,1020 h72
  text "Count" at 4208.82,1020 h72
  text "Hole Size" at 4798.66,1020 h72
  text "Plated" at 5948.33,1020 h72
  text "Hole Type" at 6454.2,1020 h72
  text "Via/Pad" at 7188,1020 h72
  text "Pad Shape" at 7777.85,1020 h72
  text "Template" at 8523.65,1020 h72
  text "Drill Layer Pair" at 9323.43,1020 h72
  text "2" at 4208.82,870 h60
  text "25.59mil (0.650mm)" at 4798.66,870 h60
  text "PTH" at 5948.33,870 h60
  text "Round" at 6454.2,870 h60
  text "Pad" at 7188,870 h60
  text "Rounded" at 7777.85,870 h60
  text "c105h65m110" at 8523.65,870 h60
  text "Top Layer - Bottom Layer" at 9323.43,870 h60
  text "2" at 4208.82,720 h60
  text "47.24mil (1.200mm)" at 4798.66,720 h60
  text "PTH" at 5948.33,720 h60
  text "Round" at 6454.2,720 h60
  text "Pad" at 7188,720 h60
  text "Rounded" at 7777.85,720 h60
  text "c200h120m207" at 8523.65,720 h60
  text "Top Layer - Bottom Layer" at 9323.43,720 h60
  text "3" at 4208.82,570 h60
  text "74.80mil (1.900mm)" at 4798.66,570 h60
  text "PTH" at 5948.33,570 h60
  text "Round" at 6454.2,570 h60
  text "Pad" at 7188,570 h60
  text "Rounded" at 7777.85,570 h60
  text "c250h190" at 8523.65,570 h60
  text "Top Layer - Bottom Layer" at 9323.43,570 h60
  text "4" at 4208.82,420 h60
  text "125.98mil (3.200mm)" at 4798.66,420 h60
  text "NPTH" at 5948.33,420 h60
  text "Round" at 6454.2,420 h60
  text "Pad" at 7188,420 h60
  text "Rounded" at 7777.85,420 h60
  text "(Mixed)" at 8523.65,420 h60
  text "Top Layer - Bottom Layer" at 9323.43,420 h60
  text "35" at 4208.82,270 h60
  text "39.37mil (1.000mm)" at 4798.66,270 h60
  text "PTH" at 5948.33,270 h60
  text "Round" at 6454.2,270 h60
  text "Pad" at 7188,270 h60
  text "(Mixed)" at 7777.85,270 h60
  text "(Mixed)" at 8523.65,270 h60
  text "Top Layer - Bottom Layer" at 9323.43,270 h60
  text "264" at 4208.82,120 h60
  text "10.00mil (0.254mm)" at 4798.66,120 h60
  text "PTH" at 5948.33,120 h60
  text "Round" at 6454.2,120 h60
  text "Via" at 7188,120 h60
  text "Rounded" at 7777.85,120 h60
  text "(Mixed)" at 8523.65,120 h60
  text "Top Layer - Bottom Layer" at 9323.43,120 h60
  text "310 Total" at 4208.82,-30 h60

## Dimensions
2700,1490 to 2600,1590 on Fabrication
2600,1590 to 2600,2040 on Fabrication
2700,1490 to 2700,200 on Fabrication
2600,100 to 2700,200 on Fabrication
2560,0 to 2600,100 on Fabrication
0,2060 to 2600,2040 on Fabrication
0,2060 to 2540,2100 on Fabrication
2560,40 to 2840,-210 on Fabrication
40,40 to -160,-130 on Fabrication
40,2060 to -160,2250 on Fabrication
40,0 to 40,2100 on Fabrication
0,40 to 2600,40 on Fabrication
0,40 to 2700,200 on Fabrication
